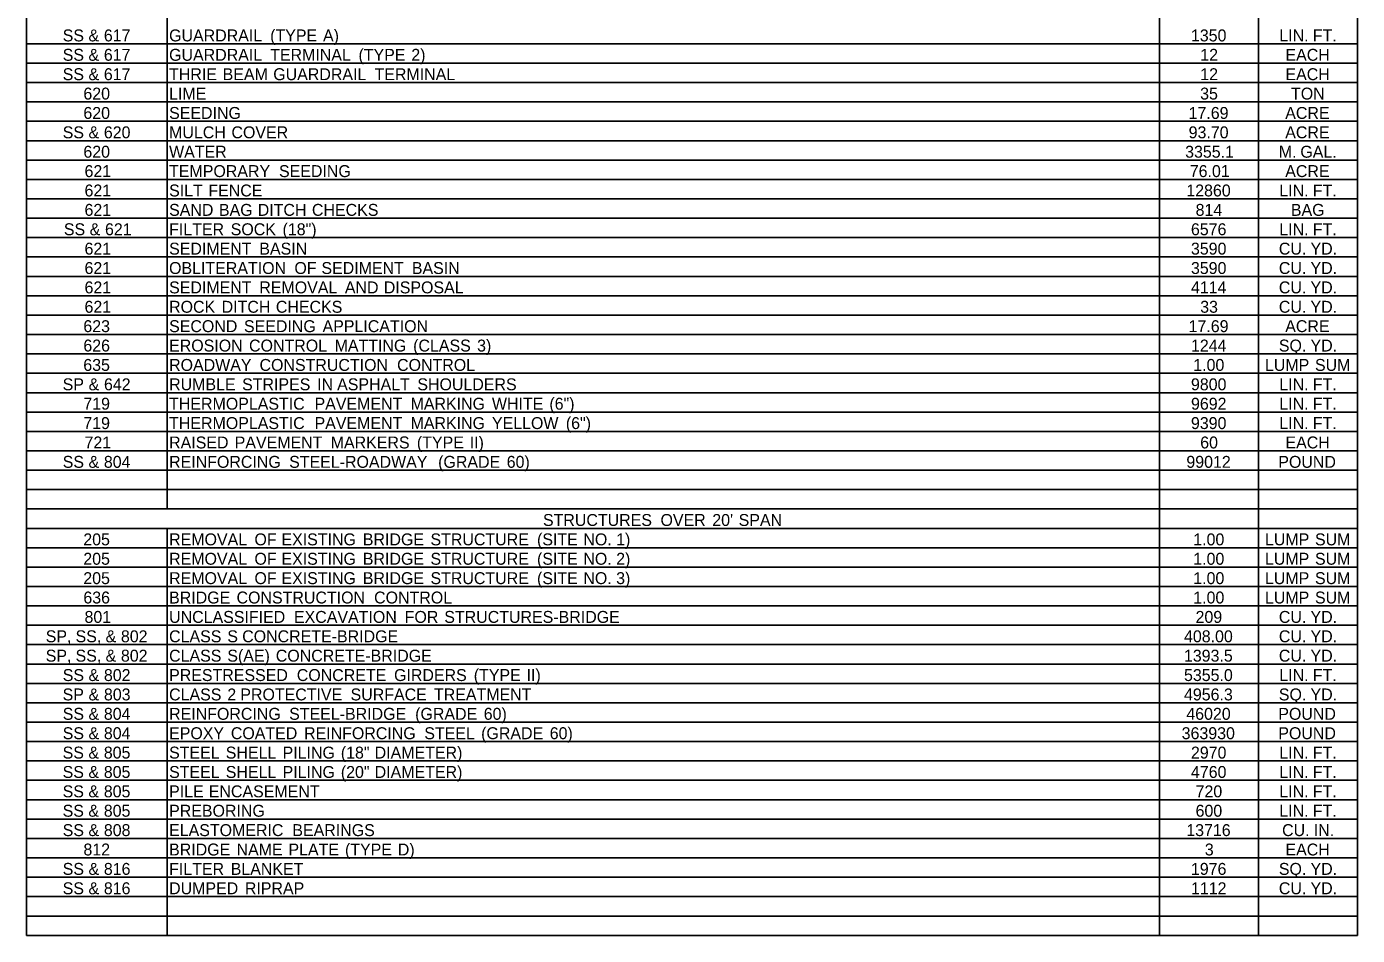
# Model space of a CAD drawing. Extents: x 977434 to 989596, y 1525697 to 1528336.
# Drawn here: x 988127 to 988796, y 1527411 to 1527868 of the extents above; entities that cross this region are included whole.
import ezdxf

# ---------------------------------------------------------------- set-up
doc = ezdxf.new("R2010")
doc.units = 0
doc.layers.add('Default', color=7, linetype='Continuous')

msp = doc.modelspace()

# ---------------------------------------------------------------- linework, layer by layer
at = {"layer": 'Default'}
for p, q in [((988126.95, 1527411.17), (988126.95, 1528298.42)), ((988126.95, 1527411.17), (988126.95, 1528298.42)), ((988197.64, 1527625.67), (988197.64, 1528298.42)), ((988696.84, 1527411.17), (988696.84, 1528298.42)), ((988746.57, 1527411.17), (988746.57, 1528298.42)), ((988746.57, 1527625.67), (988746.57, 1528298.42)), ((988796.29, 1527411.17), (988796.29, 1528298.42)), ((988197.64, 1527625.67), (988197.64, 1528269.17)), ((988696.84, 1527625.67), (988696.84, 1528269.17)), ((988126.95, 1527859.67), (988796.29, 1527859.67)), ((988126.95, 1527849.92), (988796.29, 1527849.92)), ((988126.95, 1527840.17), (988796.29, 1527840.17)), ((988126.95, 1527830.42), (988796.29, 1527830.42)), ((988126.95, 1527820.67), (988796.29, 1527820.67)), ((988126.95, 1527810.92), (988796.29, 1527810.92)), ((988126.95, 1527801.17), (988796.29, 1527801.17)), ((988126.95, 1527791.42), (988796.29, 1527791.42)), ((988126.95, 1527781.67), (988796.29, 1527781.67)), ((988126.95, 1527771.92), (988796.29, 1527771.92)), ((988126.95, 1527762.17), (988796.29, 1527762.17)), ((988126.95, 1527752.42), (988796.29, 1527752.42)), ((988126.95, 1527742.67), (988796.29, 1527742.67)), ((988126.95, 1527732.92), (988796.29, 1527732.92)), ((988126.95, 1527723.17), (988796.29, 1527723.17)), ((988126.95, 1527713.42), (988796.29, 1527713.42)), ((988126.95, 1527703.67), (988796.29, 1527703.67)), ((988126.95, 1527693.92), (988796.29, 1527693.92)), ((988126.95, 1527684.17), (988796.29, 1527684.17)), ((988126.95, 1527674.42), (988796.29, 1527674.42)), ((988126.95, 1527664.67), (988796.29, 1527664.67)), ((988126.95, 1527654.92), (988796.29, 1527654.92)), ((988126.95, 1527645.17), (988796.29, 1527645.17)), ((988126.95, 1527635.42), (988796.29, 1527635.42)), ((988126.95, 1527625.67), (988796.29, 1527625.67)), ((988746.57, 1527625.67), (988796.29, 1527625.67)), ((988126.95, 1527615.92), (988796.29, 1527615.92)), ((988197.64, 1527411.17), (988197.64, 1527615.92)), ((988197.64, 1527411.17), (988197.64, 1527615.92)), ((988696.84, 1527411.17), (988696.84, 1527615.92)), ((988746.57, 1527411.17), (988746.57, 1527615.92)), ((988126.95, 1527606.17), (988796.29, 1527606.17)), ((988126.95, 1527596.42), (988796.29, 1527596.42)), ((988126.95, 1527586.67), (988796.29, 1527586.67)), ((988126.95, 1527576.92), (988796.29, 1527576.92)), ((988126.95, 1527567.17), (988796.29, 1527567.17)), ((988126.95, 1527557.42), (988796.29, 1527557.42)), ((988126.95, 1527547.67), (988796.29, 1527547.67)), ((988126.95, 1527537.92), (988796.29, 1527537.92)), ((988126.95, 1527528.17), (988796.29, 1527528.17)), ((988126.95, 1527518.42), (988796.29, 1527518.42)), ((988126.95, 1527508.67), (988796.29, 1527508.67)), ((988126.95, 1527498.92), (988796.29, 1527498.92)), ((988126.95, 1527489.17), (988796.29, 1527489.17)), ((988126.95, 1527479.42), (988796.29, 1527479.42)), ((988126.95, 1527469.67), (988796.29, 1527469.67)), ((988126.95, 1527459.92), (988796.29, 1527459.92)), ((988126.95, 1527450.17), (988796.29, 1527450.17)), ((988126.95, 1527440.42), (988796.29, 1527440.42)), ((988126.95, 1527430.67), (988796.29, 1527430.67)), ((988126.95, 1527420.92), (988796.29, 1527420.92)), ((988126.95, 1527411.17), (988796.29, 1527411.17))]:
    msp.add_line(p, q, dxfattribs=at)

# ---------------------------------------------------------------- texts
for s, p in [('SS', (988145.1, 1527860.87)), (' &', (988155.84, 1527860.87)), (' 617', (988163.57, 1527860.87)), ('GUARDRAIL', (988198.62, 1527860.87)), (' (TYPE', (988247.23, 1527860.87)), (' A)', (988273.8, 1527860.87)), ('1350', (988712.58, 1527860.87)), ('LIN.', (988757.03, 1527860.87)), (' FT.', (988771.66, 1527860.87)), ('SS', (988145.1, 1527851.12)), (' &', (988155.84, 1527851.12)), (' 617', (988163.57, 1527851.12)), ('GUARDRAIL', (988198.62, 1527851.12)), (' TERMINAL', (988247.23, 1527851.12)), (' (TYPE', (988291.65, 1527851.12)), (' 2)', (988318.22, 1527851.12)), ('12', (988717.27, 1527851.12)), ('EACH', (988760.12, 1527851.12)), ('SS', (988145.1, 1527841.37)), (' &', (988155.84, 1527841.37)), (' 617', (988163.57, 1527841.37)), ('THRIE', (988198.62, 1527841.37)), (' BEAM', (988223.32, 1527841.37)), (' GUARDRAIL', (988248.78, 1527841.37)), (' TERMINAL', (988299.72, 1527841.37)), ('12', (988717.27, 1527841.37)), ('EACH', (988760.12, 1527841.37)), ('620', (988155.51, 1527831.62)), ('LIME', (988198.62, 1527831.62)), ('35', (988717.21, 1527831.62)), ('TON', (988762.92, 1527831.62)), ('620', (988155.51, 1527821.87)), ('SEEDING', (988198.62, 1527821.87)), ('17.69', (988711.4, 1527821.87)), ('ACRE', (988760, 1527821.87)), ('SS', (988145.11, 1527812.12)), (' &', (988155.85, 1527812.12)), (' 620', (988163.58, 1527812.12)), ('MULCH', (988198.62, 1527812.12)), (' COVER', (988227.75, 1527812.12)), ('93.70', (988711.42, 1527812.12)), ('ACRE', (988760, 1527812.12)), ('620', (988155.51, 1527802.37)), ('WATER', (988198.62, 1527802.37)), ('3355.1', (988709.66, 1527802.37)), ('M.', (988756.79, 1527802.37)), (' GAL.', (988765.37, 1527802.37)), ('621', (988156.08, 1527792.62)), ('TEMPORARY', (988198.62, 1527792.62)), (' SEEDING', (988251.66, 1527792.62)), ('76.01', (988711.99, 1527792.62)), ('ACRE', (988760, 1527792.62)), ('621', (988156.08, 1527782.87)), ('SILT', (988198.62, 1527782.87)), (' FENCE', (988216.15, 1527782.87)), ('12860', (988710.25, 1527782.87)), ('LIN.', (988757.03, 1527782.87)), (' FT.', (988771.66, 1527782.87)), ('621', (988156.08, 1527773.12)), ('SAND', (988198.62, 1527773.12)), (' BAG', (988221.46, 1527773.12)), (' DITCH', (988240.97, 1527773.12)), (' CHECKS', (988268.24, 1527773.12)), ('814', (988714.92, 1527773.12)), ('BAG', (988762.84, 1527773.12)), (' (18")', (988253.45, 1527763.37)), ('SS', (988145.68, 1527763.37)), (' &', (988156.42, 1527763.37)), (' 621', (988164.15, 1527763.37)), ('FILTER', (988198.62, 1527763.37)), (' SOCK', (988227.38, 1527763.37)), ('6576', (988712.57, 1527763.37)), ('LIN.', (988757.03, 1527763.37)), (' FT.', (988771.66, 1527763.37)), ('621', (988156.08, 1527753.62)), ('SEDIMENT', (988198.62, 1527753.62)), (' BASIN', (988241.77, 1527753.62)), ('3590', (988712.58, 1527753.62)), ('CU.', (988756.79, 1527753.62)), (' YD.', (988770.5, 1527753.62)), ('621', (988156.08, 1527743.87)), ('OBLITERATION', (988198.62, 1527743.87)), (' OF', (988259.42, 1527743.87)), (' SEDIMENT', (988273.01, 1527743.87)), (' BASIN', (988318.49, 1527743.87)), ('3590', (988712.58, 1527743.87)), ('CU.', (988756.79, 1527743.87)), (' YD.', (988770.5, 1527743.87)), ('621', (988156.08, 1527734.12)), ('SEDIMENT', (988198.62, 1527734.12)), (' REMOVAL', (988241.77, 1527734.12)), (' AND', (988284.8, 1527734.12)), (' DISPOSAL', (988304.38, 1527734.12)), ('4114', (988712.59, 1527734.12)), ('CU.', (988756.79, 1527734.12)), (' YD.', (988770.5, 1527734.12)), ('621', (988156.08, 1527724.37)), ('ROCK', (988198.62, 1527724.37)), (' DITCH', (988222.82, 1527724.37)), (' CHECKS', (988250.09, 1527724.37)), ('33', (988717.23, 1527724.37)), ('CU.', (988756.79, 1527724.37)), (' YD.', (988770.5, 1527724.37)), ('623', (988155.5, 1527714.62)), ('SECOND', (988198.62, 1527714.62)), (' SEEDING', (988234.04, 1527714.62)), (' APPLICATION', (988273.58, 1527714.62)), ('17.69', (988711.4, 1527714.62)), ('ACRE', (988760, 1527714.62)), ('626', (988155.5, 1527704.87)), ('EROSION', (988198.62, 1527704.87)), (' CONTROL', (988236.6, 1527704.87)), (' MATTING', (988279.62, 1527704.87)), (' (CLASS', (988319.14, 1527704.87)), (' 3)', (988351.31, 1527704.87)), ('1244', (988712.59, 1527704.87)), ('SQ.', (988756.79, 1527704.87)), (' YD.', (988770.5, 1527704.87)), ('635', (988155.47, 1527695.12)), ('ROADWAY', (988198.62, 1527695.12)), (' CONSTRUCTION', (988241.87, 1527695.12)), (' CONTROL', (988311.05, 1527695.12)), ('1.00', (988713.75, 1527695.12)), ('LUMP', (988749.8, 1527695.12)), (' SUM', (988772.73, 1527695.12)), ('SP', (988145.09, 1527685.37)), (' &', (988155.91, 1527685.37)), (' 642', (988163.64, 1527685.37)), ('RUMBLE', (988198.62, 1527685.37)), (' STRIPES', (988233.11, 1527685.37)), (' IN', (988270.87, 1527685.37)), (' ASPHALT', (988280.9, 1527685.37)), (' SHOULDERS', (988321.26, 1527685.37)), ('9800', (988712.58, 1527685.37)), ('LIN.', (988757.03, 1527685.37)), (' FT.', (988771.66, 1527685.37)), ('719', (988155.49, 1527675.62)), ('THERMOPLASTIC', (988198.62, 1527675.62)), (' PAVEMENT', (988269.55, 1527675.62)), (' MARKING', (988317.84, 1527675.62)), (' WHITE', (988358.77, 1527675.62)), (' (6")', (988387.66, 1527675.62)), ('9692', (988712.61, 1527675.62)), ('LIN.', (988757.03, 1527675.62)), (' FT.', (988771.66, 1527675.62)), ('719', (988155.49, 1527665.87)), ('THERMOPLASTIC', (988198.62, 1527665.87)), (' PAVEMENT', (988269.55, 1527665.87)), (' MARKING', (988317.84, 1527665.87)), (' YELLOW', (988358.77, 1527665.87)), (' (6")', (988395.94, 1527665.87)), ('9390', (988712.58, 1527665.87)), ('LIN.', (988757.03, 1527665.87)), (' FT.', (988771.66, 1527665.87)), ('721', (988156.08, 1527656.12)), ('RAISED', (988198.62, 1527656.12)), (' PAVEMENT', (988229.38, 1527656.12)), (' MARKERS', (988277.67, 1527656.12)), (' (TYPE', (988321.02, 1527656.12)), (' II)', (988347.59, 1527656.12)), ('60', (988717.24, 1527656.12)), ('EACH', (988760.12, 1527656.12)), ('SS', (988145.11, 1527646.37)), (' &', (988155.86, 1527646.37)), (' 804', (988163.58, 1527646.37)), ('REINFORCING', (988198.62, 1527646.37)), (' STEEL-ROADWAY', (988256.78, 1527646.37)), (' (GRADE', (988331.71, 1527646.37)), (' 60)', (988366.2, 1527646.37)), ('99012', (988710.28, 1527646.37)), ('POUND', (988756.51, 1527646.37)), ('STRUCTURES', (988386.66, 1527617.12)), (' OVER', (988443.55, 1527617.12)), (" 20'", (988469.59, 1527617.12)), (' SPAN', (988482.87, 1527617.12)), ('205', (988155.47, 1527607.37)), ('REMOVAL', (988198.62, 1527607.37)), (' OF', (988239.32, 1527607.37)), (' EXISTING', (988252.9, 1527607.37)), (' BRIDGE', (988293.84, 1527607.37)), (' STRUCTURE', (988327.86, 1527607.37)), (' (SITE', (988381.45, 1527607.37)), (' NO.', (988404.75, 1527607.37)), (' 1)', (988421.25, 1527607.37)), ('1.00', (988713.75, 1527607.37)), ('LUMP', (988749.8, 1527607.37)), (' SUM', (988772.73, 1527607.37)), ('205', (988155.47, 1527597.62)), ('REMOVAL', (988198.62, 1527597.62)), (' OF', (988239.32, 1527597.62)), (' EXISTING', (988252.9, 1527597.62)), (' BRIDGE', (988293.84, 1527597.62)), (' STRUCTURE', (988327.86, 1527597.62)), (' (SITE', (988381.45, 1527597.62)), (' NO.', (988404.75, 1527597.62)), (' 2)', (988421.25, 1527597.62)), ('1.00', (988713.75, 1527597.62)), ('LUMP', (988749.8, 1527597.62)), (' SUM', (988772.73, 1527597.62)), ('205', (988155.47, 1527587.87)), ('REMOVAL', (988198.62, 1527587.87)), (' OF', (988239.32, 1527587.87)), (' EXISTING', (988252.9, 1527587.87)), (' BRIDGE', (988293.84, 1527587.87)), (' STRUCTURE', (988327.86, 1527587.87)), (' (SITE', (988381.45, 1527587.87)), (' NO.', (988404.75, 1527587.87)), (' 3)', (988421.25, 1527587.87)), ('1.00', (988713.75, 1527587.87)), ('LUMP', (988749.8, 1527587.87)), (' SUM', (988772.73, 1527587.87)), ('636', (988155.5, 1527578.12)), ('BRIDGE', (988198.62, 1527578.12)), (' CONSTRUCTION', (988230.31, 1527578.12)), (' CONTROL', (988299.49, 1527578.12)), ('1.00', (988713.75, 1527578.12)), ('LUMP', (988749.8, 1527578.12)), (' SUM', (988772.73, 1527578.12)), ('801', (988156.08, 1527568.37)), ('UNCLASSIFIED', (988198.62, 1527568.37)), (' EXCAVATION', (988259.2, 1527568.37)), (' FOR', (988314.88, 1527568.37)), (' STRUCTURES-BRIDGE', (988334.8, 1527568.37)), ('209', (988714.9, 1527568.37)), ('CU.', (988756.79, 1527568.37)), (' YD.', (988770.5, 1527568.37)), ('SP,', (988136.57, 1527558.62)), (' SS,', (988149.34, 1527558.62)), (' &', (988164.43, 1527558.62)), (' 802', (988172.16, 1527558.62)), ('CLASS', (988198.62, 1527558.62)), (' S', (988225.67, 1527558.62)), (' CONCRETE-BRIDGE', (988233.15, 1527558.62)), ('408.00', (988709.09, 1527558.62)), ('CU.', (988756.79, 1527558.62)), (' YD.', (988770.5, 1527558.62)), ('SP,', (988136.57, 1527548.87)), (' SS,', (988149.34, 1527548.87)), (' &', (988164.43, 1527548.87)), (' 802', (988172.16, 1527548.87)), ('CLASS', (988198.62, 1527548.87)), (' S(AE)', (988225.67, 1527548.87)), (' CONCRETE-BRIDGE', (988250.05, 1527548.87)), ('1393.5', (988709.06, 1527548.87)), ('CU.', (988756.79, 1527548.87)), (' YD.', (988770.5, 1527548.87)), ('SS', (988145.13, 1527539.12)), (' &', (988155.87, 1527539.12)), (' 802', (988163.6, 1527539.12)), ('PRESTRESSED', (988198.62, 1527539.12)), (' CONCRETE', (988260.61, 1527539.12)), (' GIRDERS', (988309.53, 1527539.12)), (' (TYPE', (988349.62, 1527539.12)), (' II)', (988376.19, 1527539.12)), ('5355.0', (988709.09, 1527539.12)), ('LIN.', (988757.03, 1527539.12)), (' FT.', (988771.66, 1527539.12)), ('SP', (988145.06, 1527529.37)), (' &', (988155.88, 1527529.37)), (' 803', (988163.61, 1527529.37)), ('CLASS', (988198.62, 1527529.37)), (' 2', (988225.67, 1527529.37)), (' PROTECTIVE', (988232.21, 1527529.37)), (' SURFACE', (988287.67, 1527529.37)), (' TREATMENT', (988329.61, 1527529.37)), ('4956.3', (988709.08, 1527529.37)), ('SQ.', (988756.79, 1527529.37)), (' YD.', (988770.5, 1527529.37)), ('SS', (988145.11, 1527519.62)), (' &', (988155.86, 1527519.62)), (' 804', (988163.58, 1527519.62)), ('REINFORCING', (988198.62, 1527519.62)), (' STEEL-BRIDGE', (988256.78, 1527519.62)), (' (GRADE', (988320.15, 1527519.62)), (' 60)', (988354.64, 1527519.62)), ('46020', (988710.25, 1527519.62)), ('POUND', (988756.51, 1527519.62)), ('SS', (988145.11, 1527509.87)), (' &', (988155.86, 1527509.87)), (' 804', (988163.58, 1527509.87)), ('EPOXY', (988198.62, 1527509.87)), (' COATED', (988227.45, 1527509.87)), (' REINFORCING', (988264.26, 1527509.87)), (' STEEL', (988324.75, 1527509.87)), (' (GRADE', (988353.34, 1527509.87)), (' 60)', (988387.83, 1527509.87)), ('363930', (988707.92, 1527509.87)), ('POUND', (988756.51, 1527509.87)), ('SS', (988145.07, 1527500.12)), (' &', (988155.82, 1527500.12)), (' 805', (988163.55, 1527500.12)), ('STEEL', (988198.62, 1527500.12)), (' SHELL', (988224.88, 1527500.12)), (' PILING', (988253.47, 1527500.12)), (' (18"', (988282.76, 1527500.12)), (' DIAMETER)', (988299.78, 1527500.12)), ('2970', (988712.58, 1527500.12)), ('LIN.', (988757.03, 1527500.12)), (' FT.', (988771.66, 1527500.12)), ('SS', (988145.07, 1527490.37)), (' &', (988155.82, 1527490.37)), (' 805', (988163.55, 1527490.37)), ('STEEL', (988198.62, 1527490.37)), (' SHELL', (988224.88, 1527490.37)), (' PILING', (988253.47, 1527490.37)), (' (20"', (988282.76, 1527490.37)), (' DIAMETER)', (988299.78, 1527490.37)), ('4760', (988712.58, 1527490.37)), ('LIN.', (988757.03, 1527490.37)), (' FT.', (988771.66, 1527490.37)), ('SS', (988145.07, 1527480.62)), (' &', (988155.82, 1527480.62)), (' 805', (988163.55, 1527480.62)), ('PILE', (988198.62, 1527480.62)), (' ENCASEMENT', (988216.34, 1527480.62)), ('720', (988714.91, 1527480.62)), ('LIN.', (988757.03, 1527480.62)), (' FT.', (988771.66, 1527480.62)), ('SS', (988145.07, 1527470.87)), (' &', (988155.82, 1527470.87)), (' 805', (988163.55, 1527470.87)), ('PREBORING', (988198.62, 1527470.87)), ('600', (988714.91, 1527470.87)), ('LIN.', (988757.03, 1527470.87)), (' FT.', (988771.66, 1527470.87)), ('SS', (988145.09, 1527461.12)), (' &', (988155.84, 1527461.12)), (' 808', (988163.57, 1527461.12)), ('ELASTOMERIC', (988198.62, 1527461.12)), (' BEARINGS', (988258.38, 1527461.12)), ('13716', (988710.24, 1527461.12)), ('CU.', (988758.42, 1527461.12)), (' IN.', (988772.13, 1527461.12)), ('812', (988155.53, 1527451.37)), ('BRIDGE', (988198.62, 1527451.37)), (' NAME', (988230.31, 1527451.37)), (' PLATE', (988256.42, 1527451.37)), (' (TYPE', (988284.86, 1527451.37)), (' D)', (988311.43, 1527451.37)), ('3', (988719.56, 1527451.37)), ('EACH', (988760.12, 1527451.37)), ('SS', (988145.1, 1527441.62)), (' &', (988155.84, 1527441.62)), (' 816', (988163.57, 1527441.62)), ('FILTER', (988198.62, 1527441.62)), (' BLANKET', (988227.38, 1527441.62)), ('1976', (988712.57, 1527441.62)), ('SQ.', (988756.79, 1527441.62)), (' YD.', (988770.5, 1527441.62)), ('SS', (988145.1, 1527431.87)), (' &', (988155.84, 1527431.87)), (' 816', (988163.57, 1527431.87)), ('DUMPED', (988198.62, 1527431.87)), (' RIPRAP', (988234.5, 1527431.87)), ('1112', (988712.61, 1527431.87)), ('CU.', (988756.79, 1527431.87)), (' YD.', (988770.5, 1527431.87))]:
    msp.add_text(s, height=6, dxfattribs=at).set_placement(p)

doc.saveas('drawing.dxf')
